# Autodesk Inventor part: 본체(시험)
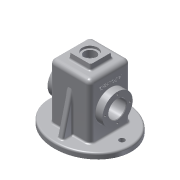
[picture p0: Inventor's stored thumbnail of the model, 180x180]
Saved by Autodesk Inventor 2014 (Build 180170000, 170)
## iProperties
Created: 2017-07
Part Number: 본체(시험)
Material: 알루미늄 6061
Document SubType Name: Modeling
Designer: 702-12
Density: 2.71 g/cm^3
Appearance: 알루미늄 - 평지
Mass: 893.713 g
Surface Area: 987.976 cm^2
Volume: 329.783 cm^3
Author: 702-12
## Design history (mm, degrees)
sketch "스케치1" dims "d0" = 75, "d1" = 65
  geometry: 2 further points; 1 other entity
  constraints: 1 coincident, 2 other
extrude "돌출1" new body sketch "스케치1" distance "d2" = 10; taper "d3" = 0 deg
sketch "스케치2"
  geometry: L1 (-37, -37)-(37, -37); L2 (37, -37)-(37, 37); L3 (37, 37)-(-37, 37); L4 (-37, 37)-(-37, -37); L5 (-37, -37)-(37, 37); L6 (37, -37)-(-37, 37); 1 further point; 1 other entity
  constraints: 12 end point, 2 midpoint, 2 parallel, 1 horizontal, 1 perpendicular, 1 other
  dimensions: "d4" = 74 distance of L3.end L2.end; "d5" = 74 distance of L2.end L1.end
extrude "돌출2" join sketch "스케치2" distance "d6" = 100; taper "d7" = 0 deg
sketch "스케치3"
  geometry: L1 (0, 74)-(-100, 74) reference; L2 (10, -28)-(10, 102) reference; C1 r 27.5 at (-45, 37); 1 further point
  constraints: 1 centre point
  dimensions: "d8" = 55 diameter of C1; "d9" = 55 distance from line of C1.centre L2; "d10" = 37 distance from line of L1 C1.centre
extrude "돌출3" join sketch "스케치3" distance "d11" = 13; taper "d12" = 0 deg
node "작업 평면1"
sketch "스케치4"
  geometry: L1 (65, 10)-(65, 0) reference; L2 (65, 0)-(-65, 0) reference; L3 (-65, 0)-(-65, 10) reference; L4 (-65, 10)-(-37, 10) reference; L5 (-37, 10)-(-37, 110) reference; L6 (-37, 110)-(37, 110) reference; L7 (37, 110)-(37, 10) reference; L8 (37, 10)-(65, 10) reference; L9 (-55, 10)-(-37, 82.194); L10 (-55, 10)-(8.14, 10); L11 (-37, 82.194)-(-37, 10); L12 (-55, 10)-(-37, 10); 1 further point
  constraints: 8 end point, 2 point on line, 1 collinear, 1 horizontal, 1 perpendicular
  dimensions: "d14" = 76 deg angle of L10 L9; "d15" = 10 distance of L3.end L9.start
extrude "돌출4" join sketch "스케치4" stored distance "d16" = 10; taper "d17" = 0 deg
node "작업 평면2"
sketch "스케치7"
  geometry: L1 (-32, -105)-(32, -105); L2 (32, -105)-(32, 105); L3 (32, 105)-(-32, 105); L4 (-32, 105)-(-32, -105); L5 (-32, -105)-(32, 105); L6 (32, -105)-(-32, 105); L7 (37, 110)-(-37, 110) reference; L8 (37, 10)-(37, 110) reference; 1 further point
  constraints: 12 end point, 2 midpoint, 2 parallel, 1 horizontal, 1 perpendicular
  dimensions: "d26" = 5 distance between parallel lines of L7 L3; "d27" = 5 distance between parallel lines of L8 L2
extrude "돌출7" cut sketch "스케치7" stored distance "d28" = 64; taper "d29" = 0 deg
sketch "스케치8"
  geometry: L1 (-37, 27.5)-(-50, 27.5) reference; L2 (-50, 27.5)-(-50, 82.5) reference; L3 (-50, 82.5)-(-37, 82.5) reference; L4 (-37, 82.5)-(-37, 110) reference; L5 (-37, 110)-(37, 110) reference; L6 (37, 110)-(37, 82.5) reference; L7 (37, 82.5)-(50, 82.5) reference; L8 (50, 82.5)-(50, 27.5) reference; L9 (50, 27.5)-(37, 27.5) reference; L10 (37, 27.5)-(37, 10) reference; L11 (37, 10)-(75, 10) reference; L12 (75, 10)-(75, 0) reference; L13 (75, 0)-(32, 0) reference; L14 (32, 0)-(32, 105) reference; L15 (32, 105)-(-32, 105) reference; L16 (-32, 105)-(-32, 0) reference; L17 (-32, 0)-(-75, 0) reference; L18 (-75, 0)-(-75, 10) reference; L19 (-75, 10)-(-37, 10) reference; L20 (-37, 10)-(-37, 27.5) reference; L21 (50, 55)-(-50, 55); L22 (32, 55)-(32, 82.5); L23 (32, 82.5)-(25, 75.5); L24 (32, 82.5)-(70.891, 82.5); L25 (25, 75.5)-(25, 55); L26 (0, 0)-(0, 105); L27 (-32, 82.5)-(-25, 75.5); L28 (-25, 75.5)-(-25, 55); L29 (-32, 55)-(-32, 82.5)
  constraints: 18 end point, 4 point on line, 4 symmetric about line, 3 midpoint, 1 horizontal, 1 perpendicular
  dimensions: "d31" = 27.5 distance of L22.start L22.end; "d32" = 135 deg angle of L23 L24
revolve "회전1" sketch "스케치8" stored, may be unused: angle "d34" = 90 deg
sketch "스케치10"
  geometry: C1 r 27.5 at (0, 0) reference; C2 r 16 at (0, 0); 1 further point
  constraints: 1 centre point, 1 coincident
  dimensions: "d38" = 32 diameter of C2
extrude "돌출9" cut sketch "스케치10" distance "d39" = 120; taper "d40" = 0 deg
sketch "스케치11"
  geometry: 5 further points
hole "구멍1" sketch "스케치11" at (-22.5, 0), (0, 22.5), (22.5, 0), (0, -22.5) diameter "d42" = 3.242; stored, may be unused: countersink angle "d46" = 90 deg, drill point angle "d48" = 118 deg; dims "d43" = 8, "d44" = 4, "d45" = 2, "d47" = 10
fillet "모깎기1" dims "d49" = 8
fillet "모깎기2" dims "d50" = 8
fillet "모깎기5" dims "d53" = 3
fillet "모깎기6" dims "d54" = 3
fillet "모깎기7" dims "d55" = 3
fillet "모깎기8" dims "d56" = 3
fillet "모깎기9" dims "d57" = 3
sketch "스케치12"
  geometry: L1 (40, -29)-(40, 29) reference; L2 (29, 40)-(8, 40) reference; L3 (8, 40)-(8, 51.16) reference; L4 (2, 57.344)-(-2, 57.344) reference; L5 (-8, 51.16)-(-8, 40) reference; L6 (-8, 40)-(-29, 40) reference; L7 (-40, 29)-(-40, -29) reference; L8 (-29, -40)-(-8, -40) reference; L9 (-8, -40)-(-8, -51.16) reference; L10 (-2, -57.344)-(2, -57.344) reference; L11 (8, -51.16)-(8, -40) reference; L12 (8, -40)-(29, -40) reference; L13 (-32, -32)-(32, -32) reference; L14 (32, -32)-(32, 32) reference; L15 (32, 32)-(-32, 32) reference; L16 (-32, 32)-(-32, -32) reference; L17 (0, 0)-(-58, 0); L18 (0, 0)-(58, 0); C1 r 5 at (-58, 0); C2 r 5 at (58, 0); A1 r 11 centre (29, -29) between (29, -40) and (40, -29) reference; A2 r 11 centre (29, 29) between (40, 29) and (29, 40) reference; A3 r 11 centre (-29, 29) between (-29, 40) and (-40, 29) reference; A4 r 11 centre (-29, -29) between (-40, -29) and (-29, -40) reference; 1 further point
  constraints: 4 end point, 2 centre point, 2 coincident, 1 collinear, 1 perpendicular, 5 other
  dimensions: "d58" = 58 distance of L17.start L17.end; "d59" = 10 diameter of C1; "d60" = 58 distance of L17.start L18.end; "d61" = 10 diameter of C2
extrude "돌출10" cut sketch "스케치12" distance "d62" = 120; taper "d63" = 0 deg
fillet "모깎기12" dims "d66" = 0.5
chamfer "모따기1" distance "d67" = 1; stored, may be unused: second distance "d68" = 2, angle "d69" = 45 deg
node "작업 평면3"
sketch "스케치13"
  geometry: L1 (-72, 10)-(-63, 10) reference; L2 (-63, 10)-(-63, 0) reference; L3 (-63, 0)-(-75, 0) reference; L4 (-75, 0)-(-75, 7) reference; L5 (75, 7)-(75, 0) reference; L6 (75, 0)-(63, 0) reference; L7 (63, 0)-(63, 10) reference; L8 (63, 10)-(72, 10) reference; L9 (39.026, 32.5)-(40, 30.879) reference; L10 (40, 30.879)-(50, 30.879) reference; L11 (50, 30.879)-(50, 27.5) reference; L12 (50, 27.5)-(37.5, 27.5) reference; L13 (37, 27)-(37, 13) reference; L14 (40, 10)-(53, 10) reference; L15 (53, 10)-(53, 0) reference; L16 (53, 0)-(32, 0) reference; L17 (32, 0)-(32, 27.293) reference; L18 (31.854, 27.646)-(25.146, 34.354) reference; L19 (25, 34.707)-(25, 39) reference; L20 (25, 39)-(49, 39) reference; L21 (49, 39)-(50, 38) reference; L22 (50, 38)-(50, 34.121) reference; L23 (50, 34.121)-(40, 34.121) reference; L24 (40, 34.121)-(39.026, 32.5) reference; L25 (-40, 30.879)-(-39.026, 32.5) reference; L26 (-39.026, 32.5)-(-40, 34.121) reference; L27 (-40, 34.121)-(-50, 34.121) reference; L28 (-50, 34.121)-(-50, 38) reference; L29 (-50, 38)-(-49, 39) reference; L30 (-49, 39)-(-25, 39) reference; L31 (-25, 39)-(-25, 34.707) reference; L32 (-25.146, 34.354)-(-31.854, 27.646) reference; L33 (-32, 27.293)-(-32, 0) reference; L34 (-32, 0)-(-53, 0) reference; L35 (-53, 0)-(-53, 10) reference; L36 (-53, 10)-(-40, 10) reference; L37 (-37, 13)-(-37, 27) reference; L38 (-37.5, 27.5)-(-50, 27.5) reference; L39 (-50, 27.5)-(-50, 30.879) reference; L40 (-50, 30.879)-(-40, 30.879) reference; L41 (-40, 75.879)-(-39.026, 77.5) reference; L42 (-39.026, 77.5)-(-40, 79.121) reference; L43 (-40, 79.121)-(-50, 79.121) reference; L44 (-50, 79.121)-(-50, 82.5) reference; L45 (-50, 82.5)-(-37.5, 82.5) reference; L46 (-37, 83)-(-37, 102) reference; L47 (-29, 110)-(29, 110) reference; L48 (37, 102)-(37, 83) reference; L49 (37.5, 82.5)-(50, 82.5) reference; L50 (50, 82.5)-(50, 79.121) reference; L51 (50, 79.121)-(40, 79.121) reference; L52 (40, 79.121)-(39.026, 77.5) reference; L53 (39.026, 77.5)-(40, 75.879) reference; L54 (40, 75.879)-(50, 75.879) reference; L55 (50, 75.879)-(50, 72) reference; L56 (50, 72)-(49, 71) reference; L57 (49, 71)-(25, 71) reference; L58 (25, 71)-(25, 75.293) reference; L59 (25.146, 75.646)-(31.854, 82.354) reference; L60 (32, 82.707)-(32, 105) reference; L61 (32, 105)-(-32, 105) reference; L62 (-32, 105)-(-32, 82.707) reference; L63 (-31.854, 82.354)-(-25.146, 75.646) reference; L64 (-25, 75.293)-(-25, 71) reference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; A1 r 0.5 centre (37.5, 27) between (37.5, 27.5) and (37, 27) reference; A2 r 3 centre (40, 13) between (37, 13) and (40, 10) reference; A3 r 0.5 centre (31.5, 27.293) between (32, 27.293) and (31.854, 27.646) reference; A4 r 0.5 centre (25.5, 34.707) between (25, 34.707) and (25.146, 34.354) reference; A5 r 0.5 centre (-25.5, 34.707) between (-25.146, 34.354) and (-25, 34.707) reference; A6 r 0.5 centre (-31.5, 27.293) between (-31.854, 27.646) and (-32, 27.293) reference; A7 r 3 centre (-40, 13) between (-40, 10) and (-37, 13) reference; A8 r 0.5 centre (-37.5, 27) between (-37, 27) and (-37.5, 27.5) reference; A9 r 0.5 centre (-37.5, 83) between (-37.5, 82.5) and (-37, 83) reference; A10 r 8 centre (-29, 102) between (-29, 110) and (-37, 102) reference; A11 r 8 centre (29, 102) between (37, 102) and (29, 110) reference; A12 r 0.5 centre (37.5, 83) between (37, 83) and (37.5, 82.5) reference; A13 r 0.5 centre (25.5, 75.293) between (25.146, 75.646) and (25, 75.293) reference; A14 r 0.5 centre (31.5, 82.707) between (31.854, 82.354) and (32, 82.707) reference; A15 r 0.5 centre (-31.5, 82.707) between (-32, 82.707) and (-31.854, 82.354) reference; A16 r 0.5 centre (-25.5, 75.293) between (-25, 75.293) and (-25.146, 75.646) reference; 1 further point
  constraints: 8 end point, 2 point on line, 2 other
  dimensions: "d74" = 40 distance of L70.end L71.end; "d94" = 5 deg angle of L46 L70
extrude "돌출11" join sketch "스케치13" stored distance "d76" = 40; taper "d77" = 0 deg
sketch "스케치14"
  geometry: C1 r 14 at (15.239, 20); 1 further point
  constraints: 1 centre point, 1 coincident
  dimensions: "d80" = 28 diameter of C1
extrude "돌출12" cut sketch "스케치14" distance "d81" = 4; taper "d82" = 0 deg
sketch "스케치15"
  geometry: C1 r 14 at (0, 0) reference; C2 r 10.5 at (0, 0)
  constraints: 1 centre point, 1 coincident
  dimensions: "d83" = 21 diameter of C2
extrude "돌출13" cut sketch "스케치15" distance "d84" = 100; taper "d85" = 0 deg
fillet "모깎기16" dims "d87" = 3
fillet "모깎기17" dims "d88" = 3
node "작업 평면4"
sketch "스케치16"
  geometry: L1 (89, 66)-(0, 66) reference; L2 (-18, 49)-(-18, 9) reference; 4 further points
  constraints: 1 other
  dimensions: "d90" = 37 distance from line of L1 point (12, 29); "d91" = 30 distance from line of L2 point (12, 29)
feature "엠보싱1" sketch "스케치16" dims "d0" = 75, "d1" = 65, "d10" = 37, "d92" = 0.5, "d93" = 0
node "작업 평면5"
sketch "스케치17"
  geometry: L1 (-37, 82.562)-(-37, 102) reference; L2 (-29, 110)-(-20, 110) reference; L3 (-20, 110)-(-20, 120) reference; L4 (-20, 120)-(-14, 120) reference; L5 (-14, 120)-(-14, 116) reference; L6 (-14, 116)-(-10.5, 116) reference; L7 (-10.5, 116)-(-10.5, 105) reference; L8 (-10.5, 105)-(-29, 105) reference; L9 (-32, 102)-(-32, 0) reference; L10 (-32, 0)-(-65, 0) reference; L11 (-65, 0)-(-65, 7) reference; L12 (-62, 10)-(-57.344, 10) reference; L13 (-54.433, 12.274)-(-37.089, 81.837) reference; L14 (37, 102)-(37, 82.562) reference; L15 (37.089, 81.837)-(54.433, 12.274) reference; L16 (57.344, 10)-(62, 10) reference; L17 (65, 7)-(65, 0) reference; L18 (65, 0)-(32, 0) reference; L19 (32, 0)-(32, 102) reference; L20 (29, 105)-(10.5, 105) reference; L21 (10.5, 105)-(10.5, 116) reference; L22 (10.5, 116)-(14, 116) reference; L23 (14, 116)-(14, 120) reference; L24 (14, 120)-(20, 120) reference; L25 (20, 120)-(20, 110) reference; L26 (20, 110)-(29, 110) reference; L27 (-20, 110)-(-18.482, 127.353); L28 (-20, 110)-(-2.581, 110); L29 (-18.482, 127.353)-(-20, 127.353); L30 (-20, 127.353)-(-20, 110); L31 (0, 120)-(0, 114.376); L32 (20, 127.353)-(20, 110); L33 (18.482, 127.353)-(20, 127.353); L34 (20, 110)-(18.482, 127.353); A1 r 8 centre (-29, 102) between (-29, 110) and (-37, 102) reference; A2 r 3 centre (-29, 102) between (-29, 105) and (-32, 102) reference; A3 r 3 centre (-57.344, 13) between (-57.344, 10) and (-54.433, 12.274) reference; A4 r 3 centre (-40, 82.562) between (-37.089, 81.837) and (-37, 82.562) reference; A5 r 3 centre (40, 82.562) between (37, 82.562) and (37.089, 81.837) reference; A6 r 3 centre (57.344, 13) between (54.433, 12.274) and (57.344, 10) reference; A7 r 3 centre (29, 102) between (32, 102) and (29, 105) reference; A8 r 8 centre (29, 102) between (37, 102) and (29, 110) reference; 1 further point
  constraints: 16 end point, 2 parallel, 2 symmetric about line, 1 collinear, 1 equal length, 1 horizontal, 2 other
  dimensions: "d96" = 85 deg angle of L28 L27
extrude "돌출14" cut sketch "스케치17" stored distance "d97" = 50; taper "d98" = 0 deg
fillet "모깎기18" dims "d99" = 3
fillet "모깎기19" dims "d100" = 3
node "솔리드1"
mirror "대칭1"
mirror "대칭2"
mirror "대칭3"
mirror "대칭4"
node "절단 모서리 투영1"
node "절단 모서리 투영2"
node "절단 모서리 투영3"
node "절단 모서리 투영4"
node "절단 모서리 투영5"
other parameters: "d13" = 0, "d18" = 0, "d33" = 7, "d70" = 0, "d89" = 1, "d95" = 0
